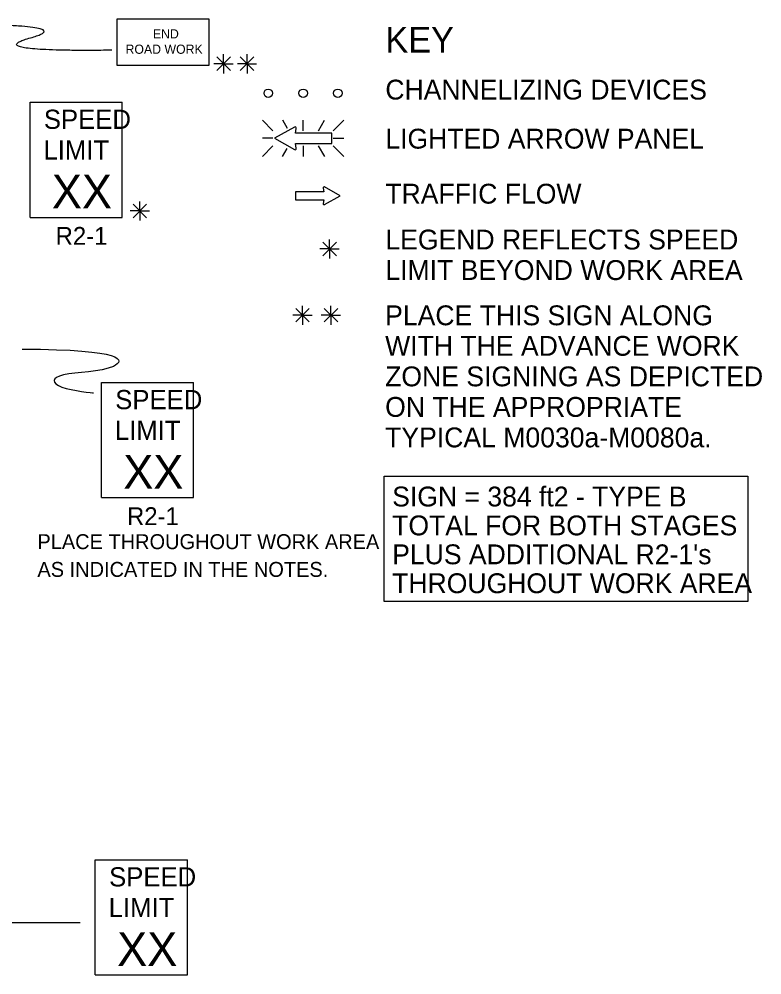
# Model space of a CAD drawing. Extents: x 16503 to 19508, y 5728 to 6974.
# Drawn here: x 17065.4 to 17413.3, y 6471 to 6919.1 of the extents above; entities that cross this region are included whole.
import ezdxf

# ---------------------------------------------------------------- set-up
doc = ezdxf.new("R2010")
doc.units = 0
for name, color, linetype in [('MT_SCRATCH_LEVEL_E', 7, 'Continuous'), ('TRAFFIC_SIGNS_PR', 7, 'Continuous'), ('TYPICAL_TEXT_DIMEN_EX', 7, 'Continuous'), ('TYPICAL_TEXT_DIMEN_PR', 7, 'Continuous')]:
    doc.layers.add(name, color=color, linetype=linetype)

msp = doc.modelspace()

# ---------------------------------------------------------------- linework, layer by layer
at = {"layer": 'MT_SCRATCH_LEVEL_E'}
for p, q in [((17208.1, 6838.14), (17194.85, 6838.14)), ((17194.85, 6838.14), (17194.85, 6834.4)), ((17207.79, 6839.92), (17208.1, 6838.14)), ((17215.71, 6836.29), (17208.47, 6840.4)), ((17194.85, 6834.4), (17208.1, 6834.4)), ((17208.1, 6834.4), (17207.79, 6832.62)), ((17208.47, 6832.15), (17215.71, 6836.29))]:
    msp.add_line(p, q, dxfattribs=at)
for centre, start, end in [((17208.25, 6839.99), 60.4248, 189.9638), ((17208.25, 6832.55), 170.0362, 299.7731)]:
    msp.add_arc(centre, 0.463, start, end, dxfattribs=at)
at = {"layer": 'TRAFFIC_SIGNS_PR'}
for p, q in [((17070.45, 6880.17), (17113.65, 6880.17)), ((17070.45, 6826.17), (17070.45, 6880.17)), ((17113.65, 6826.17), (17113.65, 6880.17)), ((17179.3, 6871.72), (17184.23, 6866.79)), ((17191.06, 6867.9), (17188.85, 6871.72)), ((17198.38, 6866.79), (17198.38, 6871.72)), ((17205.61, 6866.79), (17208.46, 6871.72)), ((17212.53, 6866.79), (17217.46, 6871.72)), ((17184.23, 6863.23), (17179.3, 6863.23)), ((17212.53, 6863.23), (17217.46, 6863.23)), ((17179.3, 6854.74), (17184.23, 6859.68)), ((17188.81, 6854.74), (17190.92, 6858.4)), ((17198.38, 6859.68), (17198.38, 6854.74)), ((17208.51, 6854.74), (17205.66, 6859.68)), ((17212.53, 6859.68), (17217.46, 6854.74)), ((17070.45, 6826.17), (17113.65, 6826.17)), ((17103.89, 6748.76), (17147.09, 6748.76)), ((17103.89, 6694.76), (17103.89, 6748.76)), ((17147.09, 6694.76), (17147.09, 6748.76)), ((17103.89, 6694.76), (17147.09, 6694.76)), ((17101.02, 6525.04), (17144.22, 6525.04)), ((17101.02, 6471.04), (17101.02, 6525.04)), ((17144.22, 6471.04), (17144.22, 6525.04)), ((17101.02, 6471.04), (17144.22, 6471.04))]:
    msp.add_line(p, q, dxfattribs=at)
msp.add_lwpolyline([(17111.13, 6897.5), (17154.33, 6897.5), (17154.33, 6919.1), (17111.13, 6919.1)], close=True, dxfattribs=at)
for points in [[(17194.31, 6868.51), (17185.01, 6863.23), (17194.31, 6857.91)], [(17195.18, 6858.54), (17194.78, 6860.81), (17211.79, 6860.81), (17211.79, 6865.61), (17194.78, 6865.61), (17195.18, 6867.89)]]:
    msp.add_lwpolyline(points, dxfattribs=at)
for centre in [(17182.09, 6884.34), (17198.39, 6884.34), (17214.69, 6884.34)]:
    msp.add_circle(centre, 2, dxfattribs=at)
for centre, radius, start, end in [((17194.59, 6867.98), 0.598, 350.7308, 118.8916), ((17194.59, 6858.43), 0.597, 241.4833, 9.9593)]:
    msp.add_arc(centre, radius, start, end, dxfattribs=at)
msp.add_open_spline([(17108.72, 6904.51), (17046.96, 6903.75), (17094.87, 6917.06), (17025.7, 6916.51)], degree=2, dxfattribs=at)
at = {"layer": 'TYPICAL_TEXT_DIMEN_EX'}
for p, q in [((17210.78, 6811.36), (17210.78, 6815.82)), ((17210.78, 6811.36), (17206.25, 6811.36)), ((17207.6, 6814.55), (17213.97, 6808.17)), ((17213.97, 6814.55), (17207.6, 6808.17)), ((17210.78, 6811.36), (17213.97, 6811.36)), ((17210.78, 6811.36), (17215.26, 6811.36)), ((17210.78, 6811.36), (17210.78, 6806.86)), ((17198.11, 6780.3), (17198.11, 6784.75)), ((17211.43, 6780.3), (17211.43, 6784.75)), ((17198.11, 6780.3), (17193.57, 6780.3)), ((17194.92, 6783.48), (17201.29, 6777.11)), ((17201.29, 6783.48), (17194.92, 6777.11)), ((17198.11, 6780.3), (17201.29, 6780.3)), ((17198.11, 6780.3), (17202.58, 6780.3)), ((17198.11, 6780.3), (17198.11, 6775.8)), ((17211.43, 6780.3), (17206.9, 6780.3)), ((17208.24, 6783.48), (17214.62, 6777.11)), ((17214.62, 6783.48), (17208.24, 6777.11)), ((17211.43, 6780.3), (17214.62, 6780.3)), ((17211.43, 6780.3), (17215.9, 6780.3)), ((17211.43, 6780.3), (17211.43, 6775.8))]:
    msp.add_line(p, q, dxfattribs=at)
msp.add_lwpolyline([(17236.42, 6704.88), (17406.78, 6704.88), (17406.78, 6646.13), (17236.42, 6646.13)], close=True, dxfattribs=at)
at = {"layer": 'TYPICAL_TEXT_DIMEN_PR'}
for p, q in [((17157.97, 6901.35), (17164.35, 6894.97)), ((17164.35, 6901.35), (17157.97, 6894.97)), ((17161.16, 6898.16), (17161.16, 6902.62)), ((17168.94, 6901.35), (17175.32, 6894.97)), ((17175.32, 6901.35), (17168.94, 6894.97)), ((17172.13, 6898.16), (17172.13, 6902.62)), ((17161.16, 6898.16), (17156.63, 6898.16)), ((17161.16, 6898.16), (17164.35, 6898.16)), ((17161.16, 6898.16), (17165.64, 6898.16)), ((17161.16, 6898.16), (17161.16, 6893.66)), ((17172.13, 6898.16), (17167.6, 6898.16)), ((17172.13, 6898.16), (17175.32, 6898.16)), ((17172.13, 6898.16), (17176.61, 6898.16)), ((17172.13, 6898.16), (17172.13, 6893.66)), ((17121.9, 6829.2), (17121.9, 6833.66)), ((17121.9, 6829.2), (17117.37, 6829.2)), ((17118.72, 6832.39), (17125.09, 6826.01)), ((17125.09, 6832.39), (17118.72, 6826.01)), ((17121.9, 6829.2), (17125.09, 6829.2)), ((17121.9, 6829.2), (17126.38, 6829.2)), ((17121.9, 6829.2), (17121.9, 6824.7)), ((17037.77, 6495.62), (17093.92, 6495.62))]:
    msp.add_line(p, q, dxfattribs=at)
msp.add_open_spline([(17066.85, 6764.37), (17115.32, 6764.37), (17115.32, 6753.62), (17080.4, 6753.62), (17080.4, 6745.79), (17100.23, 6743.84), (17100.24, 6743.84)], degree=3, dxfattribs=at)

# ---------------------------------------------------------------- texts
at = {"layer": 'TRAFFIC_SIGNS_PR'}
for s, height, p in [('END', 4.31, (17128.01, 6910.02)), ('ROAD WORK', 4.31, (17115.19, 6902.84)), ('SPEED', 9, (17076.94, 6867.64)), ('LIMIT', 9, (17076.75, 6853.24)), ('XX', 15.785, (17080.7, 6830.39)), ('R2-1', 8.37, (17082.46, 6813.3)), ('SPEED', 9, (17110.38, 6736.23)), ('LIMIT', 9, (17110.2, 6721.83)), ('XX', 15.785, (17114.15, 6698.98)), ('R2-1', 8.37, (17115.9, 6681.89)), ('PLACE THROUGHOUT WORK AREA', 7, (17073.92, 6670.63)), ('AS INDICATED IN THE NOTES.', 7, (17073.92, 6657.63)), ('SPEED', 9, (17107.51, 6512.5)), ('LIMIT', 9, (17107.33, 6498.1)), ('XX', 15.785, (17111.28, 6475.26))]:
    msp.add_text(s, height=height, dxfattribs=at).set_placement(p)
at = {"layer": 'TYPICAL_TEXT_DIMEN_EX'}
for s, height, p in [('KEY', 12, (17236.93, 6903.45)), ('CHANNELIZING DEVICES', 9.3, (17236.93, 6881.4)), ('LIGHTED ARROW PANEL', 9.3, (17236.93, 6858.4)), ('TRAFFIC FLOW', 9.3, (17236.93, 6832.61)), ('LEGEND REFLECTS SPEED', 9.31, (17236.93, 6811.11)), ('LIMIT BEYOND WORK AREA', 9.31, (17236.93, 6796.8)), ('PLACE THIS SIGN ALONG', 9.31, (17236.83, 6775.58)), ('WITH THE ADVANCE WORK', 9.31, (17236.83, 6761.27)), ('ZONE SIGNING AS DEPICTED', 9.31, (17236.83, 6746.96)), ('ON THE APPROPRIATE', 9.31, (17236.83, 6732.65)), ('TYPICAL M0030a-M0080a.', 9.31, (17236.83, 6718.34)), ('SIGN = 384 ft2 - TYPE B', 9.3, (17240.14, 6690.64)), ('TOTAL FOR BOTH STAGES', 9.3, (17240.14, 6677.09)), ("PLUS ADDITIONAL R2-1's", 9.3, (17240.14, 6663.54)), ('THROUGHOUT WORK AREA', 9.3, (17240.14, 6649.99))]:
    msp.add_text(s, height=height, dxfattribs=at).set_placement(p)

doc.saveas('drawing.dxf')
